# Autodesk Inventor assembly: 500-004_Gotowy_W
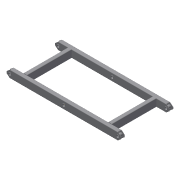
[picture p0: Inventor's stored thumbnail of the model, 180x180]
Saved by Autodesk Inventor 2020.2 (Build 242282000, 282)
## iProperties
Created: 2016-09
Part Number: 500-004_Gotowy_W
Document SubType Name: Assembly
Designer: F.Stasiak
Description: Ramię podwójne
Manager: www.cadconsulting.pl
Company: Fabian Stasiak CAD Consulting
Author: F.Stasiak
Subject: Zbiór ćwiczeń. Autodesk Inventor 2020. Kurs podstawowy
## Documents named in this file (4)
- C:\2020_Kurs_podstawowy\R6 Zespoły\Warsztat\Komponenty\500-004_Gotowy_W.iam
- C:\2020_Kurs_podstawowy\R6 Zespoły\Warsztat\Komponenty\DIN 59 410 - 500-03-04.ipt
- C:\2020_Kurs_podstawowy\R6 Zespoły\Warsztat\Komponenty\500-03-02.ipt
- C:\2020_Kurs_podstawowy\R6 Zespoły\Warsztat\Komponenty\DIN 59 410 - 500-03-03.ipt
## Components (10 placed, 3 different names)
1. DIN 59 410 - 500-03-04:1 — Kąt:1
2. DIN 59 410 - 500-03-04:2
3. 500-03-02:1 — Zestawiający:20
4. 500-03-02:2 — Zestawiający:20
5. 500-03-02:3
6. 500-03-02:4
7. 500-03-02:5 — Zestawiający:18
8. 500-03-02:6
9. DIN 59 410 - 500-03-03:1 — Zestawiający:19
10. DIN 59 410 - 500-03-03:2
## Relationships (4: Mate 3, Angle 1)
- Zestawiający:18 [Mate]: 500-03-02:5
- Kąt:1 [Angle]: DIN 59 410 - 500-03-04:1
- Zestawiający:19 [Mate]: DIN 59 410 - 500-03-03:1
- Zestawiający:20 [Mate]: 500-03-02:1 ↔ 500-03-02:2
